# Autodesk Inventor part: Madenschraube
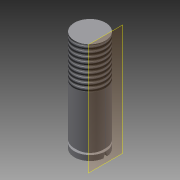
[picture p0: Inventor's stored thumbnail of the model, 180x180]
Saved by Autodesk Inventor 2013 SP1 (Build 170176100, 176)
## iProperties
Created: 2012-11
Part Number: Madenschraube
Material: Allgemein
Document SubType Name: Modeling
Designer: s0536599
Density: 1 g/cm^3
Author: s0536599
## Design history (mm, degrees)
sketch "Skizze1"
  geometry: L1 (0, -7.8)-(0, 46.8) reference; L2 (7.2, 0)-(-1.2, 0) reference; L3 (0, 0)-(6, 0); L4 (6, 0)-(6, 2); L5 (6, 2)-(5, 2); L6 (5, 2)-(5, 3); L7 (5, 3)-(6, 3); L8 (6, 3)-(6, 39); L9 (6, 39)-(0, 39); L10 (0, 39)-(0, 0)
  constraints: 16 end point, 4 perpendicular, 2 parallel, 2 point on line, 1 collinear
  dimensions: "d4" = 6 distance of L3.start L3.end; "d5" = 2 distance of L3.end L4.end; "d6" = 1 distance of L4.end L5.end; "d7" = 1 distance of L5.end L6.end; "d8" = 36 distance of L7.end L8.end; "d9" = 6 distance between parallel lines of L10 L8
revolve "Umdrehung1" sketch "Skizze1" stored, may be unused: angle "d10" = 90 deg
feature "Gewinde1" dims "d11" = 16, "d12" = 20
workplane "Arbeitsebene1"
sketch "Skizze2"
  geometry: L1 (0, -1)-(0, 1); L2 (0, 1)-(0.728, -1); L3 (0, 1)-(-0.728, -1); L4 (0, 1)-(2.128, 1); L5 (-0.728, -1)-(0.728, -1)
  constraints: 10 end point, 1 equal length, 1 horizontal, 1 parallel, 1 vertical
  dimensions: "d13" = 2 distance of L1.start L1.end; "d14" = 20 deg angle of L1 L2; "d15" = 110 deg angle of L3 L4; "d16" = 2 distance from line of L1.end L5
extrude "Extrusion1" cut sketch "Skizze2" distance "d17" = 12; taper "d18" = 0 deg
node "Volumenkörper1"
